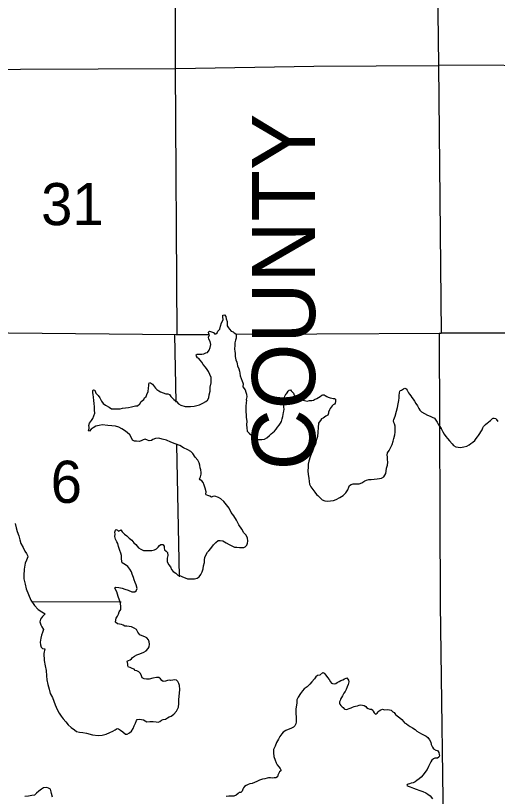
# Model space of a CAD drawing. Extents: x 77230 to 630905, y 790554 to 1662844.
# Drawn here: x 324895 to 334569, y 1607947 to 1623607 of the extents above; entities that cross this region are included whole.
import ezdxf

# ---------------------------------------------------------------- set-up
doc = ezdxf.new("R2010")
doc.units = 0
for name, color, linetype in [('Level 15', 7, 'Continuous'), ('Level 16', 7, 'Continuous'), ('Level 17', 7, 'Continuous'), ('Level 18', 7, 'Continuous'), ('Level 28', 7, 'Continuous')]:
    doc.layers.add(name, color=color, linetype=linetype)

msp = doc.modelspace()

# ---------------------------------------------------------------- linework, layer by layer
at = {"layer": 'Level 15'}
for points in [[(323399, 1617259), (328121, 1617210), (328760, 1617212)], [(329327, 1617215), (330944, 1617221)], [(330944, 1617221), (333442, 1617235)], [(339161, 1617244), (338617, 1617240), (333442, 1617235)]]:
    msp.add_lwpolyline(points, dxfattribs=at)
at = {"layer": 'Level 16'}
for points in [[(328139, 1617216), (328106, 1622551), (328091, 1627853), (328077, 1633134), (328068, 1635764)], [(323430, 1622523), (328114, 1622547), (330885, 1622592)], [(330885, 1622592), (333388, 1622603)], [(342958, 1622636), (338648, 1622586), (333384, 1622611)], [(328119, 1615852), (328093, 1617213)], [(328183, 1612351), (328134, 1614997)], [(325224, 1611854), (327014, 1611850)]]:
    msp.add_lwpolyline(points, dxfattribs=at)
at = {"layer": 'Level 17'}
for points in [[(328787, 1617279), (328811, 1617268), (328867, 1617252), (328891, 1617224), (328917, 1617225), (328941, 1617245), (328956, 1617277), (328998, 1617317), (329007, 1617378), (329032, 1617442), (329064, 1617508), (329055, 1617564), (329059, 1617596), (329089, 1617603), (329115, 1617573), (329125, 1617527), (329140, 1617471), (329144, 1617417), (329145, 1617387), (329169, 1617347), (329189, 1617319), (329226, 1617280), (329262, 1617264), (329286, 1617244), (329316, 1617221), (329326, 1617195), (329323, 1617165), (329323, 1617137), (329313, 1617099), (329300, 1617044), (329298, 1617010), (329295, 1616988), (329289, 1616922), (329296, 1616870), (329302, 1616834), (329307, 1616770), (329314, 1616700), (329334, 1616654), (329346, 1616622), (329351, 1616585), (329377, 1616525), (329392, 1616473), (329400, 1616433), (329407, 1616379), (329423, 1616329), (329442, 1616277), (329460, 1616243), (329464, 1616219), (329461, 1616163), (329502, 1616104), (329520, 1616054), (329529, 1616012), (329535, 1615962), (329526, 1615910), (329534, 1615888), (329528, 1615844), (329519, 1615768), (329518, 1615708), (329518, 1615656), (329525, 1615606), (329526, 1615544), (329540, 1615474), (329533, 1615399), (329536, 1615339), (329544, 1615273), (329585, 1615232), (329639, 1615184), (329683, 1615151), (329724, 1615115), (329776, 1615102), (329840, 1615104), (329893, 1615111), (329937, 1615141), (329990, 1615188), (330026, 1615218), (330060, 1615243), (330093, 1615273), (330129, 1615313), (330156, 1615352), (330186, 1615392), (330213, 1615434), (330231, 1615469), (330248, 1615521), (330262, 1615563), (330267, 1615603), (330275, 1615647), (330278, 1615675), (330286, 1615715), (330284, 1615753), (330283, 1615791), (330283, 1615831), (330286, 1615862), (330290, 1615892), (330294, 1615920), (330293, 1615946), (330301, 1615972), (330319, 1616012), (330335, 1616024), (330346, 1616044), (330368, 1616074), (330390, 1616097)], [(326416, 1615486), (326447, 1615524), (326466, 1615578), (326484, 1615633), (326481, 1615691), (326482, 1615763), (326470, 1615827), (326465, 1615887), (326458, 1615955), (326450, 1616005), (326445, 1616044), (326445, 1616085), (326459, 1616103), (326489, 1616097), (326509, 1616037), (326552, 1615984), (326584, 1615940), (326623, 1615876), (326655, 1615830), (326698, 1615791), (326772, 1615754), (326822, 1615720), (326870, 1615717), (326920, 1615717), (326994, 1615718), (327043, 1615730), (327103, 1615739), (327161, 1615746), (327221, 1615758), (327300, 1615779), (327340, 1615783), (327390, 1615820), (327419, 1615864), (327467, 1615909), (327484, 1615943), (327518, 1615969), (327533, 1616008), (327557, 1616068), (327566, 1616132), (327569, 1616186), (327569, 1616218), (327581, 1616250), (327607, 1616244), (327645, 1616213), (327683, 1616163), (327706, 1616133), (327734, 1616110), (327774, 1616080), (327802, 1616064), (327856, 1616043), (327914, 1616019), (327950, 1616018), (327986, 1616008), (328011, 1615968), (328037, 1615939), (328075, 1615909), (328125, 1615865), (328164, 1615822), (328216, 1615796), (328302, 1615769), (328408, 1615764), (328478, 1615773), (328537, 1615788), (328589, 1615798), (328653, 1615831), (328716, 1615868), (328746, 1615894), (328773, 1615940), (328784, 1616002), (328804, 1616073), (328801, 1616155), (328820, 1616239), (328823, 1616295), (328819, 1616351), (328794, 1616409), (328771, 1616467), (328743, 1616512), (328705, 1616556), (328664, 1616610), (328632, 1616653), (328603, 1616699), (328575, 1616727), (328547, 1616744), (328525, 1616774), (328520, 1616800), (328540, 1616818), (328588, 1616819), (328634, 1616817), (328676, 1616826), (328716, 1616840), (328751, 1616853), (328781, 1616897), (328802, 1616947), (328816, 1617011), (328799, 1617069), (328778, 1617117), (328766, 1617159), (328790, 1617201), (328777, 1617225), (328767, 1617255), (328787, 1617279)], [(332356, 1614790), (332363, 1614836), (332395, 1614885), (332430, 1614953), (332453, 1615005), (332477, 1615072), (332490, 1615128), (332509, 1615200), (332515, 1615254), (332516, 1615322), (332518, 1615372), (332505, 1615416), (332489, 1615444), (332485, 1615476), (332492, 1615506), (332515, 1615570), (332544, 1615674), (332561, 1615748), (332575, 1615821), (332588, 1615885), (332595, 1615939), (332599, 1615991), (332602, 1616037), (332608, 1616073), (332616, 1616089), (332646, 1616097), (332685, 1616118), (332713, 1616132), (332737, 1616122), (332755, 1616096), (332772, 1616065), (332786, 1616043), (332804, 1616017), (332830, 1615981), (332849, 1615947), (332879, 1615912), (332907, 1615874), (332930, 1615830), (332964, 1615777), (332991, 1615729), (333015, 1615693), (333047, 1615657), (333107, 1615624), (333163, 1615595), (333222, 1615571), (333258, 1615555), (333304, 1615530), (333336, 1615490), (333362, 1615454), (333381, 1615409), (333438, 1615323), (333472, 1615258), (333503, 1615212), (333533, 1615168), (333567, 1615126), (333608, 1615077), (333658, 1615021), (333690, 1614984), (333735, 1614960), (333779, 1614949), (333829, 1614941), (333898, 1614956), (333956, 1614968), (334004, 1614995), (334037, 1615025), (334079, 1615054), (334114, 1615088), (334144, 1615126), (334173, 1615157), (334190, 1615184)], [(330390, 1616097), (330418, 1616099), (330430, 1616079), (330454, 1616051), (330474, 1616034), (330488, 1615996), (330505, 1615984), (330547, 1615952), (330587, 1615919), (330635, 1615901), (330693, 1615884), (330749, 1615872), (330795, 1615887), (330841, 1615885), (330875, 1615896), (330898, 1615910), (330944, 1615926)], [(330944, 1615926), (331009, 1615965), (331041, 1615991), (331063, 1616002), (331091, 1616004), (331113, 1615984), (331143, 1615964), (331171, 1615953), (331209, 1615941), (331247, 1615931), (331275, 1615930), (331301, 1615928), (331319, 1615916), (331321, 1615898), (331318, 1615864), (331314, 1615836), (331296, 1615816), (331274, 1615800), (331251, 1615777), (331231, 1615755), (331209, 1615727), (331196, 1615699), (331178, 1615655), (331176, 1615631), (331171, 1615611), (331167, 1615593), (331125, 1615570), (331099, 1615554), (331068, 1615536), (331036, 1615517), (331014, 1615487), (330993, 1615455), (330977, 1615433), (330954, 1615164)], [(334190, 1615184), (334265, 1615299), (334275, 1615339), (334288, 1615367), (334312, 1615388), (334332, 1615408), (334373, 1615439), (334389, 1615453), (334407, 1615463), (334429, 1615484), (334446, 1615498), (334454, 1615506), (334472, 1615528), (334484, 1615534), (334500, 1615535), (334504, 1615535), (334536, 1615529), (334546, 1615515), (334579, 1615464)], [(328694, 1612737), (328719, 1612797), (328750, 1612842), (328778, 1612874), (328813, 1612920), (328872, 1612991), (328918, 1613037), (328963, 1613080), (329005, 1613082), (329059, 1613073), (329125, 1613030), (329182, 1613000), (329240, 1612973), (329288, 1612947), (329338, 1612942), (329390, 1612938), (329440, 1612939), (329478, 1612939), (329507, 1612953), (329537, 1612984), (329550, 1613026), (329556, 1613068), (329549, 1613132), (329521, 1613190), (329476, 1613235), (329438, 1613307), (329377, 1613390), (329332, 1613484), (329277, 1613573), (329221, 1613643), (329182, 1613729), (329127, 1613796), (329073, 1613864), (329016, 1613915), (328966, 1613943), (328896, 1613966), (328854, 1613959), (328826, 1613947), (328794, 1613965), (328756, 1613984), (328720, 1613992), (328712, 1614010), (328721, 1614054), (328701, 1614126), (328680, 1614192), (328662, 1614242), (328635, 1614273), (328603, 1614293), (328587, 1614315), (328610, 1614359), (328622, 1614409), (328618, 1614443), (328613, 1614497), (328603, 1614539), (328592, 1614593), (328582, 1614635), (328551, 1614691), (328502, 1614752), (328454, 1614824), (328412, 1614862), (328351, 1614897), (328267, 1614936), (328195, 1614982), (328099, 1615015), (328010, 1615050), (327926, 1615093), (327840, 1615114), (327772, 1615131), (327704, 1615123), (327649, 1615102), (327623, 1615082), (327579, 1615079), (327543, 1615089), (327499, 1615113), (327455, 1615098), (327418, 1615076), (327378, 1615065), (327322, 1615073), (327284, 1615072), (327240, 1615090), (327219, 1615136), (327189, 1615197), (327136, 1615243), (327080, 1615286), (327030, 1615320), (326968, 1615355), (326898, 1615371), (326830, 1615380), (326748, 1615385), (326632, 1615396), (326570, 1615387), (326507, 1615369), (326451, 1615338), (326411, 1615312), (326382, 1615273), (326362, 1615281), (326369, 1615323), (326369, 1615353), (326367, 1615387), (326378, 1615431), (326416, 1615486)], [(333430, 1615334), (333438, 1615323), (333472, 1615258), (333503, 1615212), (333533, 1615168), (333567, 1615126), (333608, 1615077), (333658, 1615021), (333690, 1614984), (333735, 1614960), (333779, 1614949), (333829, 1614941), (333898, 1614956), (333956, 1614968), (334004, 1614995), (334037, 1615025), (334079, 1615054), (334114, 1615088), (334144, 1615126), (334173, 1615157), (334190, 1615184)], [(330954, 1615164), (330931, 1615083), (330914, 1615011), (330881, 1614949), (330854, 1614869), (330832, 1614810), (330813, 1614754), (330780, 1614670), (330767, 1614613), (330767, 1614549), (330764, 1614475), (330767, 1614405), (330780, 1614331), (330790, 1614265), (330799, 1614207), (330821, 1614154), (330866, 1614100), (330904, 1614048), (330935, 1614003), (330967, 1613979)], [(330967, 1613979), (331051, 1613895), (331105, 1613876), (331167, 1613870), (331219, 1613877), (331276, 1613883), (331334, 1613902), (331407, 1613939), (331473, 1613981), (331526, 1614034), (331565, 1614094), (331587, 1614147), (331598, 1614181), (331630, 1614201), (331674, 1614217), (331738, 1614214), (331795, 1614217), (331847, 1614235), (331909, 1614274), (331942, 1614292), (331986, 1614301), (332036, 1614303), (332098, 1614308), (332155, 1614318), (332203, 1614323), (332241, 1614331), (332289, 1614358), (332310, 1614388), (332330, 1614426), (332339, 1614472), (332345, 1614532), (332360, 1614592), (332371, 1614650), (332365, 1614706), (332362, 1614754), (332356, 1614790)], [(324889, 1613417), (324904, 1613335), (324927, 1613257), (324958, 1613175), (324981, 1613093), (325001, 1613021), (325048, 1612938), (325079, 1612866), (325111, 1612820), (325136, 1612779), (325144, 1612749), (325111, 1612686), (325087, 1612622), (325067, 1612506), (325060, 1612374), (325063, 1612310), (325084, 1612204), (325109, 1612110), (325152, 1611998), (325203, 1611885), (325272, 1611777), (325351, 1611696), (325423, 1611645), (325487, 1611611), (325432, 1611555), (325393, 1611504), (325385, 1611448), (325402, 1611386), (325424, 1611347), (325453, 1611297), (325437, 1611233), (325414, 1611178), (325405, 1611122), (325386, 1611042), (325394, 1610988), (325411, 1610942), (325435, 1610914), (325479, 1610905), (325460, 1610814), (325469, 1610672), (325486, 1610565), (325507, 1610471), (325516, 1610367), (325521, 1610287), (325542, 1610191), (325567, 1610099), (325590, 1610013), (325635, 1609928), (325688, 1609786), (325727, 1609688), (325772, 1609619), (325812, 1609555), (325847, 1609503), (325903, 1609442), (325952, 1609384), (326014, 1609329), (326077, 1609282), (326121, 1609248), (326179, 1609235), (326247, 1609227), (326317, 1609214), (326441, 1609179), (326551, 1609170), (326631, 1609177), (326714, 1609196), (326790, 1609229), (326845, 1609255), (326897, 1609284), (326933, 1609306), (326962, 1609301)], [(326909, 1611486), (326917, 1611524), (326940, 1611560), (326958, 1611604), (326977, 1611647), (327007, 1611697), (327010, 1611749), (326999, 1611825), (326981, 1611879), (326956, 1611953), (326938, 1612004), (326925, 1612048), (326901, 1612094), (326886, 1612128), (326910, 1612144), (326968, 1612135), (327032, 1612120), (327088, 1612104), (327156, 1612081), (327228, 1612047), (327286, 1612050), (327314, 1612068), (327333, 1612119), (327313, 1612188), (327294, 1612236), (327276, 1612288), (327263, 1612336), (327239, 1612404), (327220, 1612452), (327188, 1612507), (327151, 1612559), (327105, 1612589), (327067, 1612608), (327035, 1612634), (327026, 1612666), (327022, 1612712), (327021, 1612776), (327009, 1612826), (326986, 1612880), (326961, 1612957), (326947, 1613017), (326928, 1613053), (326902, 1613109), (326889, 1613157), (326893, 1613205), (326890, 1613245), (326900, 1613285), (326914, 1613301), (326942, 1613283), (326958, 1613268), (326978, 1613270), (327000, 1613284), (327010, 1613296), (327034, 1613254), (327082, 1613207), (327127, 1613171), (327175, 1613126), (327227, 1613084), (327266, 1613033), (327312, 1612997), (327365, 1612932), (327413, 1612902), (327465, 1612878), (327519, 1612881), (327573, 1612878), (327629, 1612878), (327684, 1612895), (327726, 1612909), (327760, 1612946), (327787, 1612980), (327813, 1612996), (327853, 1613001), (327879, 1612965), (327879, 1612929), (327888, 1612893), (327916, 1612863), (327942, 1612835), (327951, 1612779), (327939, 1612727), (327938, 1612661), (327963, 1612595), (328003, 1612552), (328026, 1612498), (328060, 1612458), (328110, 1612425), (328155, 1612387), (328207, 1612370), (328249, 1612348), (328301, 1612327), (328349, 1612313), (328421, 1612308), (328485, 1612310), (328538, 1612321), (328582, 1612349), (328615, 1612396), (328643, 1612448), (328658, 1612508), (328667, 1612571), (328689, 1612639), (328690, 1612693), (328694, 1612737)], [(326962, 1609301), (326999, 1609273), (327045, 1609239), (327099, 1609196), (327137, 1609196), (327183, 1609219), (327220, 1609257), (327254, 1609310), (327277, 1609362), (327300, 1609416), (327324, 1609466), (327334, 1609489), (327375, 1609497), (327423, 1609486), (327465, 1609480), (327499, 1609464), (327532, 1609445), (327593, 1609447), (327657, 1609446), (327715, 1609444), (327759, 1609437), (327791, 1609451), (327823, 1609478), (327856, 1609492), (327908, 1609494), (327942, 1609523), (327978, 1609541), (328019, 1609556), (328075, 1609594), (328126, 1609657), (328167, 1609739), (328170, 1609813), (328173, 1609885), (328179, 1609954), (328186, 1610018), (328193, 1610092), (328184, 1610170), (328170, 1610212), (328150, 1610251), (328123, 1610275), (328083, 1610285), (328049, 1610276), (328008, 1610268), (327982, 1610278), (327942, 1610273), (327902, 1610257), (327858, 1610251), (327834, 1610272), (327806, 1610306), (327774, 1610332), (327722, 1610333), (327650, 1610318), (327576, 1610300), (327526, 1610301), (327479, 1610307), (327438, 1610324), (327424, 1610362), (327404, 1610414), (327369, 1610446), (327329, 1610463), (327297, 1610473), (327275, 1610495), (327239, 1610514), (327197, 1610530), (327163, 1610540), (327147, 1610565), (327148, 1610598), (327142, 1610632), (327136, 1610657), (327165, 1610672), (327197, 1610684), (327219, 1610706), (327241, 1610731), (327282, 1610757), (327332, 1610784), (327372, 1610796), (327421, 1610818), (327473, 1610841), (327514, 1610867), (327554, 1610912), (327577, 1610948), (327587, 1611002), (327580, 1611044), (327562, 1611088), (327530, 1611124), (327491, 1611147), (327439, 1611165), (327391, 1611188), (327349, 1611242), (327324, 1611294), (327274, 1611323), (327224, 1611345), (327174, 1611352), (327128, 1611358), (327086, 1611359), (327054, 1611379), (327020, 1611397), (326982, 1611400), (326940, 1611410), (326904, 1611438), (326909, 1611486)], [(331003, 1610377), (330956, 1610368), (330922, 1610344), (330896, 1610306), (330845, 1610247), (330800, 1610196), (330749, 1610144), (330691, 1610107), (330658, 1610061), (330614, 1610008), (330569, 1609938), (330544, 1609886), (330542, 1609820), (330524, 1609697), (330521, 1609627), (330528, 1609513), (330527, 1609445), (330523, 1609401), (330500, 1609361), (330472, 1609334), (330424, 1609308), (330365, 1609287), (330319, 1609271), (330267, 1609238), (330238, 1609198), (330203, 1609146), (330171, 1609091), (330132, 1609027), (330107, 1608956), (330076, 1608886), (330072, 1608820), (330083, 1608746), (330106, 1608672), (330128, 1608622), (330147, 1608577), (330179, 1608539), (330205, 1608505), (330224, 1608481), (330222, 1608461), (330192, 1608439), (330178, 1608411), (330159, 1608371), (330151, 1608340), (330122, 1608318), (330088, 1608316), (330048, 1608315), (330014, 1608321), (329972, 1608319), (329944, 1608314), (329900, 1608302), (329853, 1608289), (329793, 1608269), (329741, 1608242), (329694, 1608226), (329646, 1608207), (329596, 1608197), (329562, 1608186), (329525, 1608164), (329493, 1608142), (329471, 1608117), (329456, 1608091), (329446, 1608053), (329416, 1608025), (329386, 1608022), (329361, 1608004), (329323, 1607972), (329279, 1607951), (329236, 1607949), (329180, 1607948), (329122, 1607942)], [(331003, 1610377), (331063, 1610431), (331091, 1610415), (331125, 1610376), (331160, 1610334), (331192, 1610290), (331216, 1610247), (331237, 1610219), (331261, 1610209), (331291, 1610201), (331323, 1610210), (331354, 1610234), (331390, 1610254), (331424, 1610271), (331465, 1610287), (331497, 1610303), (331531, 1610318), (331547, 1610324), (331581, 1610276), (331587, 1610242), (331570, 1610190), (331555, 1610142), (331535, 1610092), (331514, 1610051), (331488, 1610015), (331461, 1609963), (331439, 1609927), (331419, 1609899), (331410, 1609870), (331402, 1609844), (331398, 1609814), (331403, 1609794), (331427, 1609769), (331455, 1609743), (331471, 1609731), (331491, 1609705), (331507, 1609695), (331533, 1609690), (331559, 1609694), (331591, 1609708), (331635, 1609725), (331661, 1609739), (331690, 1609747), (331722, 1609756), (331758, 1609766), (331794, 1609778), (331824, 1609783), (331858, 1609779), (331892, 1609769), (331926, 1609752), (331944, 1609730), (331972, 1609710), (332008, 1609698), (332042, 1609697), (332066, 1609677), (332078, 1609659), (332095, 1609625), (332109, 1609611), (332121, 1609599), (332137, 1609604), (332158, 1609618), (332178, 1609642), (332196, 1609662), (332228, 1609681), (332259, 1609693), (332303, 1609685), (332355, 1609692), (332401, 1609686), (332439, 1609679), (332473, 1609645), (332497, 1609629), (332524, 1609592), (332560, 1609560), (332608, 1609522), (332650, 1609491), (332681, 1609451), (332707, 1609423), (332741, 1609402), (332777, 1609376), (332818, 1609350), (332864, 1609323), (332916, 1609289), (332952, 1609256), (332998, 1609228), (333047, 1609199), (333097, 1609175), (333139, 1609154), (333171, 1609126), (333207, 1609084), (333236, 1609035), (333242, 1608989), (333267, 1608931), (333289, 1608901), (333335, 1608876), (333369, 1608864), (333395, 1608826), (333402, 1608788), (333404, 1608762), (333396, 1608732), (333369, 1608714), (333345, 1608712)], [(333345, 1608712), (333315, 1608711), (333287, 1608697), (333253, 1608671), (333232, 1608639), (333212, 1608600), (333185, 1608546), (333158, 1608488), (333112, 1608429), (333081, 1608381), (333036, 1608333), (332998, 1608298), (332951, 1608264), (332915, 1608241), (332881, 1608219), (332837, 1608209), (332802, 1608198), (332776, 1608192), (332756, 1608184), (332754, 1608162), (332780, 1608152), (332820, 1608138), (332884, 1608113), (332936, 1608089), (333012, 1608064), (333072, 1608043), (333129, 1608017), (333173, 1607994), (333219, 1607956), (333264, 1607897)], [(325636, 1607928), (325618, 1608004), (325607, 1608040), (325595, 1608092), (325555, 1608111), (325522, 1608127), (325457, 1608120), (325413, 1608092), (325364, 1608053), (325318, 1608013), (325273, 1607974), (325221, 1607962), (325153, 1607949), (325083, 1607946)]]:
    msp.add_lwpolyline(points, dxfattribs=at)
at = {"layer": 'Level 18'}
for points in [[(333256, 1632825), (333319, 1627911), (333384, 1622611), (333442, 1617235), (333402, 1617233), (333418, 1611803), (333496, 1606429), (333507, 1601178)], [(333259, 1632817), (333260, 1632530), (333319, 1627911), (333384, 1622611), (333442, 1617235), (333402, 1617233), (333418, 1611803), (333496, 1606429), (333507, 1601176)]]:
    msp.add_lwpolyline(points, dxfattribs=at)

# ---------------------------------------------------------------- texts
at = {"layer": 'Level 16'}
for s, height, p in [('31', 844.8, (325407, 1619404)), ('6', 845, (325600, 1613834))]:
    msp.add_text(s, height=height, dxfattribs=at).set_placement(p)
at = {"layer": 'Level 28'}
msp.add_text('COUNTY', height=1267.2, rotation=90, dxfattribs=at).set_placement((330909, 1614487))

doc.saveas('drawing.dxf')
